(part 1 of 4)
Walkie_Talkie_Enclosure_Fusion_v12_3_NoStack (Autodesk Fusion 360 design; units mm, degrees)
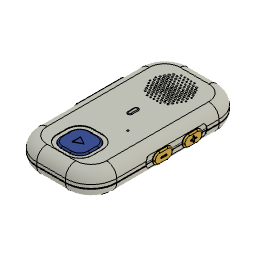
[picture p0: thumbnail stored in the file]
part number: 2026-09-08-15-04-45-721
part number: 2026-09-08-15-04-46-164
part number: 2026-09-08-15-05-02-380
part number: 2026-09-08-15-05-38-058
part number: 2026-09-08-15-05-41-092
part number: 2026-09-08-15-05-42-107
part number: 2026-09-08-15-05-45-542
part number: 2026-09-08-15-05-51-453
part number: 2026-09-08-15-05-57-566
part number: 2026-09-08-15-06-02-599
part number: 2026-09-08-15-06-07-408
part number: 2026-09-08-15-06-08-245
part number: 2026-09-08-15-06-09-018
part number: 2026-09-08-15-06-09-783
part number: 2026-09-08-15-06-10-541
part number: 2026-09-08-15-06-11-278
part number: 2026-09-08-15-06-11-947
part number: 2026-09-08-15-06-12-711
part number: 2026-09-08-15-06-13-510
part number: 2026-09-08-15-06-14-360
parameter "caseWidth" = 78 comment "Overall enclosure width"
parameter "caseHeight" = 150 comment "Overall enclosure height"
parameter "caseDepth" = 24 comment "No-stack package depth from exact installed hardware"
parameter "wallThickness" = 2.2 comment "Nominal enclosure wall"
parameter "sideControlPocketDepth" = 0.75 comment "Recess depth providing full side-button hard travel"
parameter "sideControlPocketFloor" = 1.45 comment "Minimum local side-wall floor below control recesses"
parameter "frontBackSplit" = 12 comment "Centered front/back split line"
parameter "seamOverlap" = 1.25 comment "Continuous guarded lap-seam overlap"
parameter "seamHiddenRadialClearance" = 0.2 comment "Assembly clearance concealed behind lap seam"
parameter "speakerDiameter" = 40 comment "Measured supplied Samesky frame diameter"
parameter "grilleFieldDiameter" = 39.2 comment "Approved coarse halftone W field diameter"
parameter "grillePitch" = 3.2 comment "Nearest-neighbor triangular-lattice pitch"
parameter "grilleHoleSmall" = 1.4 comment "Approved small grille perforation"
parameter "grilleHoleMedium" = 1.8 comment "Approved medium grille perforation"
parameter "grilleHoleLarge" = 2.2 comment "Approved W-core grille perforation"
parameter "grilleMinimumWeb" = 1 comment "Minimum web between adjacent 2.2 mm holes"
parameter "grilleWCoreHalfWidth" = 2.75 comment "Large-dot distance band around W centerlines"
parameter "grilleWHaloHalfWidth" = 6.5 comment "Medium-dot distance band around W centerlines"
parameter "pcbWidth" = 60.02 comment "Measured supplied PCB substrate width"
parameter "pcbHeight" = 80.02 comment "Measured supplied PCB substrate height"
parameter "fitClearance" = 0.25 comment "Per-side static FDM/SLS fit allowance"
parameter "slidingClearance" = 0.2 comment "Per-side moving-interface allowance"
parameter "buttonRestGap" = 0.14 comment "Cap-to-actuator clearance at rest"
parameter "sideSwitchMaxPretravel" = 0.45 comment "Omron B3F-3150 worst-case pretravel"
parameter "frontSwitchMaxPretravel" = 0.5 comment "Omron B3F-4000 worst-case pretravel"
parameter "sideButtonHardTravel" = 0.65 comment "Rest gap + maximum pretravel + 0.06 mm actuation margin"
parameter "frontButtonHardTravel" = 0.7 comment "Rest gap + maximum pretravel + 0.06 mm actuation margin"
parameter "sideActuatorCenterZ" = 15.2 comment "Measured installed B3F-3150 actuator center"
parameter "sideActuatorOpening" = 2.8 comment "Measured 2.40 mm actuator span plus sliding clearance"
parameter "ledBodyDiameter" = 5 comment "Measured Kingbright LED body"
parameter "ledFlangeDiameter" = 5.9 comment "Measured Kingbright LED flange"
parameter "batteryWidthMeasured" = 60.02 comment "Installed rigid battery body from supplied STL"
parameter "batteryHeightMeasured" = 36.02 comment "Installed rigid battery body from supplied STL"
parameter "batteryDepthMeasured" = 8.42 comment "Installed rigid battery body from supplied STL"
parameter "batteryBoardPlanGap" = 1.3 comment "Two fit allowances plus printable shared divider"
parameter "noStackDividerThickness" = 0.8 comment "Shared PCB +Y / battery -Y locator"
parameter "pcbNoStackShiftY" = -20.04 comment "PCB relocation eliminating battery/board overlap"
parameter "pcbFrontSwitchClearanceZ" = 0.25 comment "Clearance between front switch and shifted PCB envelope"
parameter "pcbNoStackShiftZ" = 2.77 comment "Rearward PCB shift clearing the retained front switch"
parameter "usbConnectorCenterY" = -41.0543 comment "Measured USB component center after PCB relocation"
parameter "usbConnectorCenterZ" = 15.4464 comment "Measured USB component center after PCB relocation"
parameter "usbOpeningWidth" = 9.38 comment "Measured connector Y span plus sliding clearance"
parameter "usbOpeningHeight" = 4.793 comment "Measured connector Z span plus sliding clearance"
parameter "usbShellRearDatumX" = 22.4773 comment "Exact rear face of supplied USB-C metal shell"
parameter "usbReactionClearanceX" = 0.2 comment "Connector-shell to case reaction-bridge clearance"
parameter "usbReactionPinClearanceZ" = 0.25 comment "Vertical clearance above the exact signal-pin envelope"
parameter "usbReactionBridgeThickness" = 2.2 comment "Integral back-shell USB insertion-load bridge"
parameter "usbLocalRecessDepth" = 2.7527 comment "Depth required for full 6.65 mm plug-shell seating"
parameter "minimumRibThickness" = 1.2 comment "Prototype FDM/SLS structural rib target"
parameter "minimumContactFillet" = 0.45 comment "No sharp rib at battery/film contact"
parameter "suppliedLeadMaxWidth" = 4.8 comment "Measured battery lead/connector routing envelope"
parameter "cableChannelClearWidth" = 5.3 comment "Measured lead envelope plus two fit clearances"
parameter "cableRailHeight" = 3.4 comment "Open-ended front-shell harness channel height"
parameter "speakerGasketPocketDepth" = 0.3 comment "Closed-cell acoustic gasket seat depth"
parameter "microphoneGasketPocketDepth" = 0.3 comment "Acoustic gasket/mesh seat depth"
parameter "batterySoftPadPocketDepth" = 0.45 comment "Replaceable nonabrasive foam-pad location"
parameter "batteryServiceReliefWidth" = 20 comment "Central removal access between retained top-rail lands"
parameter "rearWordmarkWidth" = 42 comment "Text-only WALKIE ONE wordmark from supplied lockup"
parameter "rearWordmarkCenterY" = -52 comment "Final WALKIE ONE vertical position"
parameter "rearWordmarkDebossDepth" = 0.35 comment "Shallow printable rear engraving"
parameter "rearTaglineHeight" = 1.6 comment "Small upright Designed in Los Angeles lettering"
parameter "rearTaglineCenterY" = -58.5 comment "Centered origin line beneath WALKIE ONE"
parameter "rearTaglineDebossDepth" = 0.25 comment "Subordinate shallow rear engraving"
sketch "Outer Housing" plane through (0, 0, 0) normal (0, 0, 1) x axis (1, 0, 0)
  line L1 (14, -75) -> (-14, -75)
  line L2 (39, 50) -> (39, -50)
  line L3 (-14, 75) -> (14, 75)
  line L4 (-39, -50) -> (-39, 50)
  arc A1 centre (14, -50) radius 25 clockwise from (39, -50) to (14, -75)
  arc A2 centre (14, 50) radius 25 clockwise from (14, 75) to (39, 50)
  arc A3 centre (-14, 50) radius 25 clockwise from (-39, 50) to (-14, 75)
  arc A4 centre (-14, -50) radius 25 clockwise from (-14, -75) to (-39, -50)
extrude "Extrude1" new body sketch "Outer Housing" blind 12
fillet "Fillet1" radius 10
sketch "Front Cavity" plane through (0, 0, 0) normal (0, 0, 1) x axis (1, 0, 0)
  line L1 (14, -72.8) -> (-14, -72.8)
  line L2 (36.8, 50) -> (36.8, -50)
  line L3 (-14, 72.8) -> (14, 72.8)
  line L4 (-36.8, -50) -> (-36.8, 50)
  arc A1 centre (14, -50) radius 22.8 clockwise from (36.8, -50) to (14, -72.8)
  arc A2 centre (14, 50) radius 22.8 clockwise from (14, 72.8) to (36.8, 50)
  arc A3 centre (-14, 50) radius 22.8 clockwise from (-36.8, 50) to (-14, 72.8)
  arc A4 centre (-14, -50) radius 22.8 clockwise from (-14, -72.8) to (-36.8, -50)
extrude "Extrude2" new body sketch "Front Cavity" blind 10 from offset 2.2
fillet "Fillet2" radius 7.8
combine "Combine1"
sketch "Continuous Exterior Seam Guard Collar Sketch" plane through (0, 0, 0) normal (0, 0, 1) x axis (1, 0, 0)
  line L1 (14, -75) -> (-14, -75)
  line L2 (39, 50) -> (39, -50)
  line L3 (-14, 75) -> (14, 75)
  line L4 (-39, -50) -> (-39, 50)
  line L5 (14, -74) -> (-14, -74)
  line L6 (38, 50) -> (38, -50)
  line L7 (-14, 74) -> (14, 74)
  line L8 (-38, -50) -> (-38, 50)
  arc A1 centre (14, -50) radius 25 clockwise from (39, -50) to (14, -75)
  arc A2 centre (14, 50) radius 25 clockwise from (14, 75) to (39, 50)
  arc A3 centre (-14, 50) radius 25 clockwise from (-39, 50) to (-14, 75)
  arc A4 centre (-14, -50) radius 25 clockwise from (-14, -75) to (-39, -50)
  arc A5 centre (14, -50) radius 24 clockwise from (38, -50) to (14, -74)
  arc A6 centre (14, 50) radius 24 clockwise from (14, 74) to (38, 50)
  arc A7 centre (-14, 50) radius 24 clockwise from (-38, 50) to (-14, 74)
  arc A8 centre (-14, -50) radius 24 clockwise from (-14, -74) to (-38, -50)
extrude "Extrude3" add sketch "Continuous Exterior Seam Guard Collar Sketch" blind 1.65 from offset 11.6
sketch "Speaker Seat Solid Sketch" plane through (0, 0, 0) normal (0, 0, 1) x axis (1, 0, 0)
  circle C1 centre (0, 42) radius 23
extrude "Extrude4" add sketch "Speaker Seat Solid Sketch" blind 2.2 from offset 1.6
sketch "Speaker Seat Center Pocket Sketch" plane through (0, 0, 0) normal (0, 0, 1) x axis (1, 0, 0)
  circle C1 centre (0, 42) radius 20.3
extrude "Extrude5" cut sketch "Speaker Seat Center Pocket Sketch" blind 1.8 from offset 2.2
sketch "Speaker Terminal Hidden Relief Sketch" plane through (0, 0, 0) normal (0, 0, 1) x axis (1, 0, 0)
  line L1 (6.2, 18.45) -> (-6.2, 18.45)
  line L2 (6.5, 22.95) -> (6.5, 18.75)
  line L3 (-6.2, 23.25) -> (6.2, 23.25)
  line L4 (-6.5, 18.75) -> (-6.5, 22.95)
  arc A1 centre (6.2, 18.75) radius 0.3 clockwise from (6.5, 18.75) to (6.2, 18.45)
  arc A2 centre (6.2, 22.95) radius 0.3 clockwise from (6.2, 23.25) to (6.5, 22.95)
  arc A3 centre (-6.2, 22.95) radius 0.3 clockwise from (-6.5, 22.95) to (-6.2, 23.25)
  arc A4 centre (-6.2, 18.75) radius 0.3 clockwise from (-6.2, 18.45) to (-6.5, 18.75)
extrude "Extrude6" cut sketch "Speaker Terminal Hidden Relief Sketch" blind 1.9 from offset 2.2
sketch "Speaker Terminal Hidden Relief Sketch (1)" plane through (0, 0, 0) normal (0, 0, 1) x axis (1, 0, 0)
  line L1 (6.2, 58.75) -> (-6.2, 58.75)
  line L2 (6.5, 69.25) -> (6.5, 59.05)
  line L3 (-6.2, 69.55) -> (6.2, 69.55)
  line L4 (-6.5, 59.05) -> (-6.5, 69.25)
  arc A1 centre (6.2, 59.05) radius 0.3 clockwise from (6.5, 59.05) to (6.2, 58.75)
  arc A2 centre (6.2, 69.25) radius 0.3 clockwise from (6.2, 69.55) to (6.5, 69.25)
  arc A3 centre (-6.2, 69.25) radius 0.3 clockwise from (-6.5, 69.25) to (-6.2, 69.55)
  arc A4 centre (-6.2, 59.05) radius 0.3 clockwise from (-6.2, 58.75) to (-6.5, 59.05)
extrude "Extrude7" cut sketch "Speaker Terminal Hidden Relief Sketch (1)" blind 1.9 from offset 2.2
sketch "Speaker Acoustic Gasket Pocket Sketch" plane through (0, 0, 0) normal (0, 0, 1) x axis (1, 0, 0)
  circle C1 centre (0, 42) radius 22.1
  circle C2 centre (0, 42) radius 20.3
extrude "Extrude8" cut sketch "Speaker Acoustic Gasket Pocket Sketch" blind 0.3 from offset 2.2
sketch "Speaker Snap Post Sketch" plane through (0, 0, 0) normal (0, 0, 1) x axis (1, 0, 0)
  circle C1 centre (15.27, 57.27) radius 1.5
extrude "Extrude9" add sketch "Speaker Snap Post Sketch" blind 5.75 from offset 2
sketch "Speaker Snap Lip Sketch" plane through (0, 0, 0) normal (0, 0, 1) x axis (1, 0, 0)
  circle C1 centre (15.27, 57.27) radius 2.1
extrude "Extrude10" add sketch "Speaker Snap Lip Sketch" blind 0.45 from offset 7.45
sketch "Speaker Snap Post Sketch (1)" plane through (0, 0, 0) normal (0, 0, 1) x axis (1, 0, 0)
  circle C1 centre (-15.27, 57.27) radius 1.5
extrude "Extrude11" add sketch "Speaker Snap Post Sketch (1)" blind 5.75 from offset 2
sketch "Speaker Snap Lip Sketch (1)" plane through (0, 0, 0) normal (0, 0, 1) x axis (1, 0, 0)
  circle C1 centre (-15.27, 57.27) radius 2.1
extrude "Extrude12" add sketch "Speaker Snap Lip Sketch (1)" blind 0.45 from offset 7.45
sketch "Speaker Snap Post Sketch (2)" plane through (0, 0, 0) normal (0, 0, 1) x axis (1, 0, 0)
  circle C1 centre (15.27, 26.73) radius 1.5
extrude "Extrude13" add sketch "Speaker Snap Post Sketch (2)" blind 5.75 from offset 2
sketch "Speaker Snap Lip Sketch (2)" plane through (0, 0, 0) normal (0, 0, 1) x axis (1, 0, 0)
  circle C1 centre (15.27, 26.73) radius 2.1
extrude "Extrude14" add sketch "Speaker Snap Lip Sketch (2)" blind 0.45 from offset 7.45
sketch "Speaker Snap Post Sketch (3)" plane through (0, 0, 0) normal (0, 0, 1) x axis (1, 0, 0)
  circle C1 centre (-15.27, 26.73) radius 1.5
extrude "Extrude15" add sketch "Speaker Snap Post Sketch (3)" blind 5.75 from offset 2
sketch "Speaker Snap Lip Sketch (3)" plane through (0, 0, 0) normal (0, 0, 1) x axis (1, 0, 0)
  circle C1 centre (-15.27, 26.73) radius 2.1
extrude "Extrude16" add sketch "Speaker Snap Lip Sketch (3)" blind 0.45 from offset 7.45
sketch "Coarse Three-Size Halftone W Grille 01" plane through (0, 0, 0) normal (0, 0, 1) x axis (1, 0, 0)
  circle C1 centre (-6.4, 25.3723) radius 0.7
  circle C2 centre (-3.2, 25.3723) radius 0.7
  circle C3 centre (0, 25.3723) radius 0.7
  circle C4 centre (3.2, 25.3723) radius 0.7
  circle C5 centre (6.4, 25.3723) radius 0.7
  circle C6 centre (-11.2, 28.1436) radius 0.9
  circle C7 centre (-8, 28.1436) radius 0.9
  circle C8 centre (-4.8, 28.1436) radius 0.9
  circle C9 centre (-1.6, 28.1436) radius 0.7
  circle C10 centre (1.6, 28.1436) radius 0.7
  circle C11 centre (4.8, 28.1436) radius 0.9
  circle C12 centre (8, 28.1436) radius 0.9
  circle C13 centre (11.2, 28.1436) radius 0.9
  circle C14 centre (-12.8, 30.9149) radius 0.9
  circle C15 centre (-9.6, 30.9149) radius 0.9
  circle C16 centre (-6.4, 30.9149) radius 1.1
  circle C17 centre (-3.2, 30.9149) radius 0.9
  circle C18 centre (0, 30.9149) radius 0.7
  circle C19 centre (3.2, 30.9149) radius 0.9
  circle C20 centre (6.4, 30.9149) radius 1.1
  circle C21 centre (9.6, 30.9149) radius 0.9
  circle C22 centre (12.8, 30.9149) radius 0.9
  circle C23 centre (-14.4, 33.6862) radius 0.7
  circle C24 centre (-11.2, 33.6862) radius 0.9
  circle C25 centre (-8, 33.6862) radius 1.1
  circle C26 centre (-4.8, 33.6862) radius 1.1
  circle C27 centre (-1.6, 33.6862) radius 0.9
  circle C28 centre (1.6, 33.6862) radius 0.9
  circle C29 centre (4.8, 33.6862) radius 1.1
  circle C30 centre (8, 33.6862) radius 1.1
  circle C31 centre (11.2, 33.6862) radius 0.9
  circle C32 centre (14.4, 33.6862) radius 0.7
  circle C33 centre (-16, 36.4574) radius 0.7
  circle C34 centre (-12.8, 36.4574) radius 0.9
  circle C35 centre (-9.6, 36.4574) radius 1.1
  circle C36 centre (-6.4, 36.4574) radius 1.1
  circle C37 centre (-3.2, 36.4574) radius 1.1
  circle C38 centre (0, 36.4574) radius 0.9
  circle C39 centre (3.2, 36.4574) radius 1.1
  circle C40 centre (6.4, 36.4574) radius 1.1
  circle C41 centre (9.6, 36.4574) radius 1.1
  circle C42 centre (12.8, 36.4574) radius 0.9
  circle C43 centre (16, 36.4574) radius 0.7
  circle C44 centre (-17.6, 39.2287) radius 0.7
  circle C45 centre (-14.4, 39.2287) radius 0.9
  circle C46 centre (-11.2, 39.2287) radius 1.1
  circle C47 centre (-8, 39.2287) radius 1.1
  circle C48 centre (-4.8, 39.2287) radius 1.1
  circle C49 centre (-1.6, 39.2287) radius 1.1
  circle C50 centre (1.6, 39.2287) radius 1.1
  circle C51 centre (4.8, 39.2287) radius 1.1
  circle C52 centre (8, 39.2287) radius 1.1
  circle C53 centre (11.2, 39.2287) radius 1.1
  circle C54 centre (14.4, 39.2287) radius 0.9
  circle C55 centre (17.6, 39.2287) radius 0.7
  circle C56 centre (-16, 42) radius 0.9
  circle C57 centre (-12.8, 42) radius 0.9
  circle C58 centre (-9.6, 42) radius 1.1
  circle C59 centre (-6.4, 42) radius 0.9
  circle C60 centre (-3.2, 42) radius 1.1
  circle C61 centre (0, 42) radius 1.1
  circle C62 centre (3.2, 42) radius 1.1
  circle C63 centre (6.4, 42) radius 0.9
  circle C64 centre (9.6, 42) radius 1.1
  circle C65 centre (12.8, 42) radius 0.9
  circle C66 centre (16, 42) radius 0.9
  circle C67 centre (-17.6, 44.7713) radius 0.7
  circle C68 centre (-14.4, 44.7713) radius 0.9
  circle C69 centre (-11.2, 44.7713) radius 1.1
  circle C70 centre (-8, 44.7713) radius 1.1
  circle C71 centre (-4.8, 44.7713) radius 0.9
  circle C72 centre (-1.6, 44.7713) radius 1.1
  circle C73 centre (1.6, 44.7713) radius 1.1
  circle C74 centre (4.8, 44.7713) radius 0.9
  circle C75 centre (8, 44.7713) radius 1.1
  circle C76 centre (11.2, 44.7713) radius 1.1
  circle C77 centre (14.4, 44.7713) radius 0.9
  circle C78 centre (17.6, 44.7713) radius 0.7
  circle C79 centre (-16, 47.5426) radius 0.9
  circle C80 centre (-12.8, 47.5426) radius 1.1
  circle C81 centre (-9.6, 47.5426) radius 1.1
  circle C82 centre (-6.4, 47.5426) radius 0.9
  circle C83 centre (-3.2, 47.5426) radius 0.9
  circle C84 centre (0, 47.5426) radius 0.9
  circle C85 centre (3.2, 47.5426) radius 0.9
  circle C86 centre (6.4, 47.5426) radius 0.9
  circle C87 centre (9.6, 47.5426) radius 1.1
  circle C88 centre (12.8, 47.5426) radius 1.1
  circle C89 centre (16, 47.5426) radius 0.9
  circle C90 centre (-14.4, 50.3138) radius 1.1
  circle C91 centre (-11.2, 50.3138) radius 1.1
  circle C92 centre (-8, 50.3138) radius 0.9
  circle C93 centre (-4.8, 50.3138) radius 0.7
  circle C94 centre (-1.6, 50.3138) radius 0.7
  circle C95 centre (1.6, 50.3138) radius 0.7
  circle C96 centre (4.8, 50.3138) radius 0.7
  circle C97 centre (8, 50.3138) radius 0.9
  circle C98 centre (11.2, 50.3138) radius 1.1
  circle C99 centre (14.4, 50.3138) radius 1.1
  circle C100 centre (-12.8, 53.0851) radius 1.1
  circle C101 centre (-9.6, 53.0851) radius 0.9
  circle C102 centre (-6.4, 53.0851) radius 0.9
  circle C103 centre (-3.2, 53.0851) radius 0.7
  circle C104 centre (0, 53.0851) radius 0.7
  circle C105 centre (3.2, 53.0851) radius 0.7
  circle C106 centre (6.4, 53.0851) radius 0.9
  circle C107 centre (9.6, 53.0851) radius 0.9
  circle C108 centre (12.8, 53.0851) radius 1.1
  circle C109 centre (-11.2, 55.8564) radius 0.9
  circle C110 centre (-8, 55.8564) radius 0.9
  circle C111 centre (-4.8, 55.8564) radius 0.7
  circle C112 centre (-1.6, 55.8564) radius 0.7
  circle C113 centre (1.6, 55.8564) radius 0.7
  circle C114 centre (4.8, 55.8564) radius 0.7
  circle C115 centre (8, 55.8564) radius 0.9
  circle C116 centre (11.2, 55.8564) radius 0.9
  circle C117 centre (-6.4, 58.6277) radius 0.7
  circle C118 centre (-3.2, 58.6277) radius 0.7
  circle C119 centre (0, 58.6277) radius 0.7
  circle C120 centre (3.2, 58.6277) radius 0.7
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extrude "Extrude17" cut sketch "Coarse Three-Size Halftone W Grille 01" blind 3.2
sketch "Quiet Orb Status Light Opening Sketch" plane through (0, 0, 0) normal (0, 0, 1) x axis (1, 0, 0)
  line L1 (0.05, -0.2) -> (-0.05, -0.2)
  line L2 (2.2, 8.05) -> (2.2, 1.95)
  line L3 (-0.05, 10.2) -> (0.05, 10.2)
  line L4 (-2.2, 1.95) -> (-2.2, 8.05)
  arc A1 centre (0.05, 1.95) radius 2.15 clockwise from (2.2, 1.95) to (0.05, -0.2)
  arc A2 centre (0.05, 8.05) radius 2.15 clockwise from (0.05, 10.2) to (2.2, 8.05)
  arc A3 centre (-0.05, 8.05) radius 2.15 clockwise from (-2.2, 8.05) to (-0.05, 10.2)
  arc A4 centre (-0.05, 1.95) radius 2.15 clockwise from (-0.05, -0.2) to (-2.2, 1.95)
extrude "Extrude18" cut sketch "Quiet Orb Status Light Opening Sketch" blind 3
sketch "Microphone Port Sketch" plane through (0, 0, 0) normal (0, 0, 1) x axis (1, 0, 0)
  circle C1 centre (-14, -14) radius 0.9
extrude "Extrude19" cut sketch "Microphone Port Sketch" blind 3.2
sketch "Microphone Acoustic Gasket Pocket Sketch" plane through (0, 0, 0) normal (0, 0, 1) x axis (1, 0, 0)
  circle C1 centre (-14, -14) radius 2.75
  circle C2 centre (-14, -14) radius 1.1
extrude "Extrude20" cut sketch "Microphone Acoustic Gasket Pocket Sketch" blind 0.35 from offset 1.9
sketch "Sculpted Action Thumb Well Sketch" plane through (0, 0, 0) normal (0, 0, 1) x axis (1, 0, 0)
  line L1 (5, -64.5) -> (-5, -64.5)
  line L2 (17.5, -42) -> (17.5, -52)
  line L3 (-5, -29.5) -> (5, -29.5)
  line L4 (-17.5, -52) -> (-17.5, -42)
  arc A1 centre (5, -52) radius 12.5 clockwise from (17.5, -52) to (5, -64.5)
  arc A2 centre (5, -42) radius 12.5 clockwise from (5, -29.5) to (17.5, -42)
  arc A3 centre (-5, -42) radius 12.5 clockwise from (-17.5, -42) to (-5, -29.5)
  arc A4 centre (-5, -52) radius 12.5 clockwise from (-5, -64.5) to (-17.5, -52)
extrude "Extrude21" cut sketch "Sculpted Action Thumb Well Sketch" blind 0.58
sketch "Quiet Orb Action Button Opening Sketch" plane through (0, 0, 0) normal (0, 0, 1) x axis (1, 0, 0)
  line L1 (4.4, -61.1) -> (-4.4, -61.1)
  line L2 (14.1, -42.6) -> (14.1, -51.4)
  line L3 (-4.4, -32.9) -> (4.4, -32.9)
  line L4 (-14.1, -51.4) -> (-14.1, -42.6)
  arc A1 centre (4.4, -51.4) radius 9.7 clockwise from (14.1, -51.4) to (4.4, -61.1)
  arc A2 centre (4.4, -42.6) radius 9.7 clockwise from (4.4, -32.9) to (14.1, -42.6)
  arc A3 centre (-4.4, -42.6) radius 9.7 clockwise from (-14.1, -42.6) to (-4.4, -32.9)
  arc A4 centre (-4.4, -51.4) radius 9.7 clockwise from (-4.4, -61.1) to (-14.1, -51.4)
extrude "Extrude22" cut sketch "Quiet Orb Action Button Opening Sketch" blind 3
sketch "LED Guide Tube Solid Sketch" plane through (0, 0, 0) normal (0, 0, 1) x axis (1, 0, 0)
  circle C1 centre (0, 5) radius 4
extrude "Extrude23" add sketch "LED Guide Tube Solid Sketch" blind 8.9 from offset 1.8
sketch "LED Body Guide Bore Sketch" plane through (0, 0, 0) normal (0, 0, 1) x axis (1, 0, 0)
  circle C1 centre (0, 5) radius 2.65
extrude "Extrude24" cut sketch "LED Body Guide Bore Sketch" blind 7 from offset 2.05
sketch "LED Flange Pocket Sketch" plane through (0, 0, 0) normal (0, 0, 1) x axis (1, 0, 0)
  circle C1 centre (0, 5) radius 3.2
extrude "Extrude25" cut sketch "LED Flange Pocket Sketch" blind 2 from offset 9.05
sketch "LED Flange Flex Post Sketch" plane through (0, 0, 0) normal (0, 0, 1) x axis (1, 0, 0)
  line L1 (-3.57, 3.9) -> (-3.73, 3.9)
  line L2 (-3.15, 5.68) -> (-3.15, 4.32)
  line L3 (-3.73, 6.1) -> (-3.57, 6.1)
  line L4 (-4.15, 4.32) -> (-4.15, 5.68)
  arc A1 centre (-3.57, 4.32) radius 0.42 clockwise from (-3.15, 4.32) to (-3.57, 3.9)
  arc A2 centre (-3.57, 5.68) radius 0.42 clockwise from (-3.57, 6.1) to (-3.15, 5.68)
  arc A3 centre (-3.73, 5.68) radius 0.42 clockwise from (-4.15, 5.68) to (-3.73, 6.1)
  arc A4 centre (-3.73, 4.32) radius 0.42 clockwise from (-3.73, 3.9) to (-4.15, 4.32)
extrude "Extrude26" add sketch "LED Flange Flex Post Sketch" blind 2.3 from offset 8.8
sketch "LED Flange Flex Post Sketch (1)" plane through (0, 0, 0) normal (0, 0, 1) x axis (1, 0, 0)
  line L1 (3.73, 3.9) -> (3.57, 3.9)
  line L2 (4.15, 5.68) -> (4.15, 4.32)
  line L3 (3.57, 6.1) -> (3.73, 6.1)
  line L4 (3.15, 4.32) -> (3.15, 5.68)
  arc A1 centre (3.73, 4.32) radius 0.42 clockwise from (4.15, 4.32) to (3.73, 3.9)
  arc A2 centre (3.73, 5.68) radius 0.42 clockwise from (3.73, 6.1) to (4.15, 5.68)
  arc A3 centre (3.57, 5.68) radius 0.42 clockwise from (3.15, 5.68) to (3.57, 6.1)
  arc A4 centre (3.57, 4.32) radius 0.42 clockwise from (3.57, 3.9) to (3.15, 4.32)
extrude "Extrude27" add sketch "LED Flange Flex Post Sketch (1)" blind 2.3 from offset 8.8
sketch "LED Captive Flange Hook Sketch" plane through (0, 0, 0) normal (0, 0, 1) x axis (1, 0, 0)
  line L1 (-2.87, 3.9) -> (-3.73, 3.9)
  line L2 (-2.45, 5.68) -> (-2.45, 4.32)
  line L3 (-3.73, 6.1) -> (-2.87, 6.1)
  line L4 (-4.15, 4.32) -> (-4.15, 5.68)
  arc A1 centre (-2.87, 4.32) radius 0.42 clockwise from (-2.45, 4.32) to (-2.87, 3.9)
  arc A2 centre (-2.87, 5.68) radius 0.42 clockwise from (-2.87, 6.1) to (-2.45, 5.68)
  arc A3 centre (-3.73, 5.68) radius 0.42 clockwise from (-4.15, 5.68) to (-3.73, 6.1)
  arc A4 centre (-3.73, 4.32) radius 0.42 clockwise from (-3.73, 3.9) to (-4.15, 4.32)
extrude "Extrude28" add sketch "LED Captive Flange Hook Sketch" blind 0.5 from offset 10.55
sketch "LED Captive Flange Hook Sketch (1)" plane through (0, 0, 0) normal (0, 0, 1) x axis (1, 0, 0)
  line L1 (3.73, 3.9) -> (2.87, 3.9)
  line L2 (4.15, 5.68) -> (4.15, 4.32)
  line L3 (2.87, 6.1) -> (3.73, 6.1)
  line L4 (2.45, 4.32) -> (2.45, 5.68)
  arc A1 centre (3.73, 4.32) radius 0.42 clockwise from (4.15, 4.32) to (3.73, 3.9)
  arc A2 centre (3.73, 5.68) radius 0.42 clockwise from (3.73, 6.1) to (4.15, 5.68)
  arc A3 centre (2.87, 5.68) radius 0.42 clockwise from (2.45, 5.68) to (2.87, 6.1)
  arc A4 centre (2.87, 4.32) radius 0.42 clockwise from (2.87, 3.9) to (2.45, 4.32)
extrude "Extrude29" add sketch "LED Captive Flange Hook Sketch (1)" blind 0.5 from offset 10.55
sketch "Restore Quiet Orb Status Aperture Sketch" plane through (0, 0, 0) normal (0, 0, 1) x axis (1, 0, 0)
  line L1 (0.05, -0.2) -> (-0.05, -0.2)
  line L2 (2.2, 8.05) -> (2.2, 1.95)
  line L3 (-0.05, 10.2) -> (0.05, 10.2)
  line L4 (-2.2, 1.95) -> (-2.2, 8.05)
  arc A1 centre (0.05, 1.95) radius 2.15 clockwise from (2.2, 1.95) to (0.05, -0.2)
  arc A2 centre (0.05, 8.05) radius 2.15 clockwise from (0.05, 10.2) to (2.2, 8.05)
  arc A3 centre (-0.05, 8.05) radius 2.15 clockwise from (-2.2, 8.05) to (-0.05, 10.2)
  arc A4 centre (-0.05, 1.95) radius 2.15 clockwise from (-0.05, -0.2) to (-2.2, 1.95)
extrude "Extrude30" cut sketch "Restore Quiet Orb Status Aperture Sketch" blind 3.2
sketch "Microphone Breakout Pocket Sketch" plane through (0, 0, 0) normal (0, 0, 1) x axis (1, 0, 0)
  line L1 (-6.4, -21.2) -> (-21.6, -21.2)
  line L2 (-4.9, -8.3) -> (-4.9, -19.7)
  line L3 (-21.6, -6.8) -> (-6.4, -6.8)
  line L4 (-23.1, -19.7) -> (-23.1, -8.3)
  line L5 (-6.55, -20.6) -> (-21.45, -20.6)
  line L6 (-5.5, -8.45) -> (-5.5, -19.55)
  line L7 (-21.45, -7.4) -> (-6.55, -7.4)
  line L8 (-22.5, -19.55) -> (-22.5, -8.45)
  arc A1 centre (-6.4, -19.7) radius 1.5 clockwise from (-4.9, -19.7) to (-6.4, -21.2)
  arc A2 centre (-6.4, -8.3) radius 1.5 clockwise from (-6.4, -6.8) to (-4.9, -8.3)
  arc A3 centre (-21.6, -8.3) radius 1.5 clockwise from (-23.1, -8.3) to (-21.6, -6.8)
  arc A4 centre (-21.6, -19.7) radius 1.5 clockwise from (-21.6, -21.2) to (-23.1, -19.7)
  arc A5 centre (-6.55, -19.55) radius 1.05 clockwise from (-5.5, -19.55) to (-6.55, -20.6)
  arc A6 centre (-6.55, -8.45) radius 1.05 clockwise from (-6.55, -7.4) to (-5.5, -8.45)
  arc A7 centre (-21.45, -8.45) radius 1.05 clockwise from (-22.5, -8.45) to (-21.45, -7.4)
  arc A8 centre (-21.45, -19.55) radius 1.05 clockwise from (-21.45, -20.6) to (-22.5, -19.55)
extrude "Extrude31" add sketch "Microphone Breakout Pocket Sketch" blind 3.2 from offset 2
sketch "Microphone Snap Lip Sketch" plane through (0, 0, 0) normal (0, 0, 1) x axis (1, 0, 0)
  line L1 (-12.5, -20.9) -> (-15.5, -20.9)
  line L2 (-12, -20.1) -> (-12, -20.4)
  line L3 (-15.5, -19.6) -> (-12.5, -19.6)
  line L4 (-16, -20.4) -> (-16, -20.1)
  arc A1 centre (-12.5, -20.4) radius 0.5 clockwise from (-12, -20.4) to (-12.5, -20.9)
  arc A2 centre (-12.5, -20.1) radius 0.5 clockwise from (-12.5, -19.6) to (-12, -20.1)
  arc A3 centre (-15.5, -20.1) radius 0.5 clockwise from (-16, -20.1) to (-15.5, -19.6)
  arc A4 centre (-15.5, -20.4) radius 0.5 clockwise from (-15.5, -20.9) to (-16, -20.4)
extrude "Extrude32" add sketch "Microphone Snap Lip Sketch" blind 0.4 from offset 4.95
sketch "Microphone Snap Lip Sketch (1)" plane through (0, 0, 0) normal (0, 0, 1) x axis (1, 0, 0)
  line L1 (-12.5, -8.4) -> (-15.5, -8.4)
  line L2 (-12, -7.6) -> (-12, -7.9)
  line L3 (-15.5, -7.1) -> (-12.5, -7.1)
  line L4 (-16, -7.9) -> (-16, -7.6)
  arc A1 centre (-12.5, -7.9) radius 0.5 clockwise from (-12, -7.9) to (-12.5, -8.4)
  arc A2 centre (-12.5, -7.6) radius 0.5 clockwise from (-12.5, -7.1) to (-12, -7.6)
  arc A3 centre (-15.5, -7.6) radius 0.5 clockwise from (-16, -7.6) to (-15.5, -7.1)
  arc A4 centre (-15.5, -7.9) radius 0.5 clockwise from (-15.5, -8.4) to (-16, -7.9)
extrude "Extrude33" add sketch "Microphone Snap Lip Sketch (1)" blind 0.4 from offset 4.95
sketch "Front Switch Clamp Boss Sketch" plane through (0, 0, 0) normal (0, 0, 1) x axis (1, 0, 0)
  circle C1 centre (-17, -47) radius 2.1
extrude "Extrude34" add sketch "Front Switch Clamp Boss Sketch" blind 8.85 from offset 2
sketch "Front Switch Clamp M2 Pilot Sketch" plane through (0, 0, 0) normal (0, 0, 1) x axis (1, 0, 0)
  circle C1 centre (-17, -47) radius 0.85
extrude "Extrude35" cut sketch "Front Switch Clamp M2 Pilot Sketch" blind 8.4 from offset 2.6
sketch "Front Switch Clamp Boss Sketch (1)" plane through (0, 0, 0) normal (0, 0, 1) x axis (1, 0, 0)
  circle C1 centre (17, -47) radius 2.1
extrude "Extrude36" add sketch "Front Switch Clamp Boss Sketch (1)" blind 8.85 from offset 2
sketch "Front Switch Clamp M2 Pilot Sketch (1)" plane through (0, 0, 0) normal (0, 0, 1) x axis (1, 0, 0)
  circle C1 centre (17, -47) radius 0.85
extrude "Extrude37" cut sketch "Front Switch Clamp M2 Pilot Sketch (1)" blind 8.4 from offset 2.6
sketch "Front Switch Body Reaction Bridge Sketch" plane through (0, 0, 0) normal (0, 0, 1) x axis (1, 0, 0)
  line L1 (16.5, -55) -> (-16.5, -55)
  line L2 (19.5, -42) -> (19.5, -52)
  line L3 (-16.5, -39) -> (16.5, -39)
  line L4 (-19.5, -52) -> (-19.5, -42)
  line L5 (2, -51) -> (-2, -51)
  line L6 (4, -45) -> (4, -49)
  line L7 (-2, -43) -> (2, -43)
  line L8 (-4, -49) -> (-4, -45)
  arc A1 centre (16.5, -52) radius 3 clockwise from (19.5, -52) to (16.5, -55)
  arc A2 centre (16.5, -42) radius 3 clockwise from (16.5, -39) to (19.5, -42)
  arc A3 centre (-16.5, -42) radius 3 clockwise from (-19.5, -42) to (-16.5, -39)
  arc A4 centre (-16.5, -52) radius 3 clockwise from (-16.5, -55) to (-19.5, -52)
  arc A5 centre (2, -49) radius 2 clockwise from (4, -49) to (2, -51)
  arc A6 centre (2, -45) radius 2 clockwise from (2, -43) to (4, -45)
  arc A7 centre (-2, -45) radius 2 clockwise from (-4, -45) to (-2, -43)
  arc A8 centre (-2, -49) radius 2 clockwise from (-2, -51) to (-4, -49)
extrude "Extrude38" add sketch "Front Switch Body Reaction Bridge Sketch" blind 0.2 from offset 3.2
sketch "PTT Interaction Field Sketch" plane through (0, 0, 0) normal (1, 0, 0) x axis (0, 0, -1)
  line L1 (-11.9, -17.5) -> (-12.1, -17.5)
  line L2 (-5.1, 34.7) -> (-5.1, -10.7)
  line L3 (-12.1, 41.5) -> (-11.9, 41.5)
  line L4 (-18.9, -10.7) -> (-18.9, 34.7)
  arc A1 centre (-11.9, -10.7) radius 6.8 clockwise from (-5.1, -10.7) to (-11.9, -17.5)
  arc A2 centre (-11.9, 34.7) radius 6.8 clockwise from (-11.9, 41.5) to (-5.1, 34.7)
  arc A3 centre (-12.1, 34.7) radius 6.8 clockwise from (-18.9, 34.7) to (-12.1, 41.5)
  arc A4 centre (-12.1, -10.7) radius 6.8 clockwise from (-12.1, -17.5) to (-18.9, -10.7)
extrude "Extrude39" cut sketch "PTT Interaction Field Sketch" blind -0.75 (= "-( 0.75 mm )") from offset 39.2
sketch "Unified Volume Interaction Field Sketch" plane through (0, 0, 0) normal (1, 0, 0) x axis (0, 0, -1)
  line L1 (-11.9, -21.25) -> (-12.1, -21.25)
  line L2 (-5.1, 31.45) -> (-5.1, -14.45)
  line L3 (-12.1, 38.25) -> (-11.9, 38.25)
  line L4 (-18.9, -14.45) -> (-18.9, 31.45)
  arc A1 centre (-11.9, -14.45) radius 6.8 clockwise from (-5.1, -14.45) to (-11.9, -21.25)
  arc A2 centre (-11.9, 31.45) radius 6.8 clockwise from (-11.9, 38.25) to (-5.1, 31.45)
  arc A3 centre (-12.1, 31.45) radius 6.8 clockwise from (-18.9, 31.45) to (-12.1, 38.25)
  arc A4 centre (-12.1, -14.45) radius 6.8 clockwise from (-12.1, -21.25) to (-18.9, -14.45)
extrude "Extrude40" cut sketch "Unified Volume Interaction Field Sketch" blind 0.75 from offset -39.2
sketch "Left PTT Through Opening Sketch" plane through (0, 0, 0) normal (1, 0, 0) x axis (0, 0, -1)
  line L1 (-11.9, -13.2) -> (-12.1, -13.2)
  line L2 (-7.5, 32.8) -> (-7.5, -8.8)
  line L3 (-12.1, 37.2) -> (-11.9, 37.2)
  line L4 (-16.5, -8.8) -> (-16.5, 32.8)
  arc A1 centre (-11.9, -8.8) radius 4.4 clockwise from (-7.5, -8.8) to (-11.9, -13.2)
  arc A2 centre (-11.9, 32.8) radius 4.4 clockwise from (-11.9, 37.2) to (-7.5, 32.8)
  arc A3 centre (-12.1, 32.8) radius 4.4 clockwise from (-16.5, 32.8) to (-12.1, 37.2)
  arc A4 centre (-12.1, -8.8) radius 4.4 clockwise from (-12.1, -13.2) to (-16.5, -8.8)
extrude "Extrude41" cut sketch "Left PTT Through Opening Sketch" blind 40
sketch "Volume Up Through Opening Sketch" plane through (0, 0, 0) normal (1, 0, 0) x axis (0, 0, -1)
  line L1 (-11.9, 15.15) -> (-12.1, 15.15)
  line L2 (-7.8, 26.75) -> (-7.8, 19.25)
  line L3 (-12.1, 30.85) -> (-11.9, 30.85)
  line L4 (-16.2, 19.25) -> (-16.2, 26.75)
  arc A1 centre (-11.9, 19.25) radius 4.1 clockwise from (-7.8, 19.25) to (-11.9, 15.15)
  arc A2 centre (-11.9, 26.75) radius 4.1 clockwise from (-11.9, 30.85) to (-7.8, 26.75)
  arc A3 centre (-12.1, 26.75) radius 4.1 clockwise from (-16.2, 26.75) to (-12.1, 30.85)
  arc A4 centre (-12.1, 19.25) radius 4.1 clockwise from (-12.1, 15.15) to (-16.2, 19.25)
extrude "Extrude42" cut sketch "Volume Up Through Opening Sketch" blind -40 (= "-( 40.00 mm )")
sketch "Volume Down Through Opening Sketch" plane through (0, 0, 0) normal (1, 0, 0) x axis (0, 0, -1)
  line L1 (-11.9, -13.85) -> (-12.1, -13.85)
  line L2 (-7.8, -2.25) -> (-7.8, -9.75)
  line L3 (-12.1, 1.85) -> (-11.9, 1.85)
  line L4 (-16.2, -9.75) -> (-16.2, -2.25)
  arc A1 centre (-11.9, -9.75) radius 4.1 clockwise from (-7.8, -9.75) to (-11.9, -13.85)
  arc A2 centre (-11.9, -2.25) radius 4.1 clockwise from (-11.9, 1.85) to (-7.8, -2.25)
  arc A3 centre (-12.1, -2.25) radius 4.1 clockwise from (-16.2, -2.25) to (-12.1, 1.85)
  arc A4 centre (-12.1, -9.75) radius 4.1 clockwise from (-12.1, -13.85) to (-16.2, -9.75)
extrude "Extrude43" cut sketch "Volume Down Through Opening Sketch" blind -40 (= "-( 40.00 mm )")
sketch "USB-C Full-Seating Local Wall Recess Sketch" plane through (0, 0, 0) normal (1, 0, 0) x axis (0, 0, -1)
  line L1 (-15.1964, -47.6793) -> (-15.6964, -47.6793)
  line L2 (-11.7464, -37.8793) -> (-11.7464, -44.2293)
  line L3 (-15.6964, -34.4293) -> (-15.1964, -34.4293)
  line L4 (-19.1464, -44.2293) -> (-19.1464, -37.8793)
  arc A1 centre (-15.1964, -44.2293) radius 3.45 clockwise from (-11.7464, -44.2293) to (-15.1964, -47.6793)
  arc A2 centre (-15.1964, -37.8793) radius 3.45 clockwise from (-15.1964, -34.4293) to (-11.7464, -37.8793)
  arc A3 centre (-15.6964, -37.8793) radius 3.45 clockwise from (-19.1464, -37.8793) to (-15.6964, -34.4293)
  arc A4 centre (-15.6964, -44.2293) radius 3.45 clockwise from (-15.6964, -47.6793) to (-19.1464, -44.2293)
extrude "Extrude44" cut sketch "USB-C Full-Seating Local Wall Recess Sketch" blind -2.9527 (= "-( 2.952733 mm )") from offset 39.2
sketch "Sketch45" plane through (0, 0, 0) normal (1, 0, 0) x axis (0, 0, -1)
  line L1 (-15.3964, -45.7443) -> (-15.4964, -45.7443)
  line L2 (-13.0499, -38.7108) -> (-13.0499, -43.3978)
  line L3 (-15.4964, -36.3643) -> (-15.3964, -36.3643)
  line L4 (-17.8429, -43.3978) -> (-17.8429, -38.7108)
  arc A1 centre (-15.3964, -43.3978) radius 2.3465 clockwise from (-13.0499, -43.3978) to (-15.3964, -45.7443)
  arc A2 centre (-15.3964, -38.7108) radius 2.3465 clockwise from (-15.3964, -36.3643) to (-13.0499, -38.7108)
  arc A3 centre (-15.4964, -38.7108) radius 2.3465 clockwise from (-17.8429, -38.7108) to (-15.4964, -36.3643)
  arc A4 centre (-15.4964, -43.3978) radius 2.3465 clockwise from (-15.4964, -45.7443) to (-17.8429, -43.3978)
extrude "Extrude45" cut sketch "Sketch45" blind 40
sketch "PTT Internal Switch Body Clearance Sketch" plane through (0, 0, 0) normal (1, 0, 0) x axis (0, 0, -1)
  line L1 (-8.49, 6.65) -> (-18.01, 6.65)
  line L2 (-8.04, 16.9) -> (-8.04, 7.1)
  line L3 (-18.01, 17.35) -> (-8.49, 17.35)
  line L4 (-18.46, 7.1) -> (-18.46, 16.9)
  arc A1 centre (-8.49, 7.1) radius 0.45 clockwise from (-8.04, 7.1) to (-8.49, 6.65)
  arc A2 centre (-8.49, 16.9) radius 0.45 clockwise from (-8.49, 17.35) to (-8.04, 16.9)
  arc A3 centre (-18.01, 16.9) radius 0.45 clockwise from (-18.46, 16.9) to (-18.01, 17.35)
  arc A4 centre (-18.01, 7.1) radius 0.45 clockwise from (-18.01, 6.65) to (-18.46, 7.1)
extrude "Extrude46" cut sketch "PTT Internal Switch Body Clearance Sketch" blind 5.1 from offset 31.9
sketch "PTT Switch Cage Anchor Sketch" plane through (0, 0, 0) normal (0, 0, 1) x axis (1, 0, 0)
  line L1 (32, 6.45) -> (31.5, 6.45)
  line L2 (32.35, 7.3) -> (32.35, 6.8)
  line L3 (31.5, 7.65) -> (32, 7.65)
  line L4 (31.15, 6.8) -> (31.15, 7.3)
  arc A1 centre (32, 6.8) radius 0.35 clockwise from (32.35, 6.8) to (32, 6.45)
  arc A2 centre (32, 7.3) radius 0.35 clockwise from (32, 7.65) to (32.35, 7.3)
  arc A3 centre (31.5, 7.3) radius 0.35 clockwise from (31.15, 7.3) to (31.5, 7.65)
  arc A4 centre (31.5, 6.8) radius 0.35 clockwise from (31.5, 6.45) to (31.15, 6.8)
extrude "Extrude47" add sketch "PTT Switch Cage Anchor Sketch" blind 5.59 from offset 2
sketch "PTT Switch Cage Anchor Sketch (1)" plane through (0, 0, 0) normal (0, 0, 1) x axis (1, 0, 0)
  line L1 (32, 16.35) -> (31.5, 16.35)
  line L2 (32.35, 17.2) -> (32.35, 16.7)
  line L3 (31.5, 17.55) -> (32, 17.55)
  line L4 (31.15, 16.7) -> (31.15, 17.2)
  arc A1 centre (32, 16.7) radius 0.35 clockwise from (32.35, 16.7) to (32, 16.35)
  arc A2 centre (32, 17.2) radius 0.35 clockwise from (32, 17.55) to (32.35, 17.2)
  arc A3 centre (31.5, 17.2) radius 0.35 clockwise from (31.15, 17.2) to (31.5, 17.55)
  arc A4 centre (31.5, 16.7) radius 0.35 clockwise from (31.5, 16.35) to (31.15, 16.7)
extrude "Extrude48" add sketch "PTT Switch Cage Anchor Sketch (1)" blind 5.59 from offset 2
sketch "PTT Switch Floor Sketch" plane through (0, 0, 0) normal (0, 0, 1) x axis (1, 0, 0)
  line L1 (36.65, 6.65) -> (31.55, 6.65)
  line L2 (37.1, 16.9) -> (37.1, 7.1)
  line L3 (31.55, 17.35) -> (36.65, 17.35)
  line L4 (31.1, 7.1) -> (31.1, 16.9)
  arc A1 centre (36.65, 7.1) radius 0.45 clockwise from (37.1, 7.1) to (36.65, 6.65)
  arc A2 centre (36.65, 16.9) radius 0.45 clockwise from (36.65, 17.35) to (37.1, 16.9)
  arc A3 centre (31.55, 16.9) radius 0.45 clockwise from (31.1, 16.9) to (31.55, 17.35)
  arc A4 centre (31.55, 7.1) radius 0.45 clockwise from (31.55, 6.65) to (31.1, 7.1)
extrude "Extrude49" add sketch "PTT Switch Floor Sketch" blind 0.55 from offset 7.49
sketch "PTT Switch Inward Backstop Sketch" plane through (0, 0, 0) normal (0, 0, 1) x axis (1, 0, 0)
  line L1 (31.85, 6.65) -> (31.65, 6.65)
  line L2 (32.2, 17) -> (32.2, 7)
  line L3 (31.65, 17.35) -> (31.85, 17.35)
  line L4 (31.3, 7) -> (31.3, 17)
  arc A1 centre (31.85, 7) radius 0.35 clockwise from (32.2, 7) to (31.85, 6.65)
  arc A2 centre (31.85, 17) radius 0.35 clockwise from (31.85, 17.35) to (32.2, 17)
  arc A3 centre (31.65, 17) radius 0.35 clockwise from (31.3, 17) to (31.65, 17.35)
  arc A4 centre (31.65, 7) radius 0.35 clockwise from (31.65, 6.65) to (31.3, 7)
extrude "Extrude50" add sketch "PTT Switch Inward Backstop Sketch" blind 4.51 from offset 7.49
sketch "PTT Switch Side Rail Sketch" plane through (0, 0, 0) normal (0, 0, 1) x axis (1, 0, 0)
  line L1 (36.675, 6.65) -> (32.325, 6.65)
  line L2 (36.975, 7.15) -> (36.975, 6.95)
  line L3 (32.325, 7.45) -> (36.675, 7.45)
  line L4 (32.025, 6.95) -> (32.025, 7.15)
  arc A1 centre (36.675, 6.95) radius 0.3 clockwise from (36.975, 6.95) to (36.675, 6.65)
  arc A2 centre (36.675, 7.15) radius 0.3 clockwise from (36.675, 7.45) to (36.975, 7.15)
  arc A3 centre (32.325, 7.15) radius 0.3 clockwise from (32.025, 7.15) to (32.325, 7.45)
  arc A4 centre (32.325, 6.95) radius 0.3 clockwise from (32.325, 6.65) to (32.025, 6.95)
extrude "Extrude51" add sketch "PTT Switch Side Rail Sketch" blind 4.51 from offset 7.49
sketch "PTT Switch Side Rail Sketch (1)" plane through (0, 0, 0) normal (0, 0, 1) x axis (1, 0, 0)
  line L1 (36.675, 16.55) -> (32.325, 16.55)
  line L2 (36.975, 17.05) -> (36.975, 16.85)
  line L3 (32.325, 17.35) -> (36.675, 17.35)
  line L4 (32.025, 16.85) -> (32.025, 17.05)
  arc A1 centre (36.675, 16.85) radius 0.3 clockwise from (36.975, 16.85) to (36.675, 16.55)
  arc A2 centre (36.675, 17.05) radius 0.3 clockwise from (36.675, 17.35) to (36.975, 17.05)
  arc A3 centre (32.325, 17.05) radius 0.3 clockwise from (32.025, 17.05) to (32.325, 17.35)
  arc A4 centre (32.325, 16.85) radius 0.3 clockwise from (32.325, 16.55) to (32.025, 16.85)
extrude "Extrude52" add sketch "PTT Switch Side Rail Sketch (1)" blind 4.51 from offset 7.49
sketch "PTT Switch Actuator Shoulder Sketch" plane through (0, 0, 0) normal (0, 0, 1) x axis (1, 0, 0)
  line L1 (37.28, 6.65) -> (37.22, 6.65)
  line L2 (37.5, 17.13) -> (37.5, 6.87)
  line L3 (37.22, 17.35) -> (37.28, 17.35)
  line L4 (37, 6.87) -> (37, 17.13)
  arc A1 centre (37.28, 6.87) radius 0.22 clockwise from (37.5, 6.87) to (37.28, 6.65)
  arc A2 centre (37.28, 17.13) radius 0.22 clockwise from (37.28, 17.35) to (37.5, 17.13)
  arc A3 centre (37.22, 17.13) radius 0.22 clockwise from (37, 17.13) to (37.22, 17.35)
  arc A4 centre (37.22, 6.87) radius 0.22 clockwise from (37.22, 6.65) to (37, 6.87)
extrude "Extrude53" add sketch "PTT Switch Actuator Shoulder Sketch" blind 4.51 from offset 7.49
sketch "PTT Actuator Passage Sketch" plane through (0, 0, 0) normal (1, 0, 0) x axis (0, 0, -1)
  line L1 (-14.4, 10.6) -> (-16, 10.6)
  line L2 (-13.8, 12.8) -> (-13.8, 11.2)
  line L3 (-16, 13.4) -> (-14.4, 13.4)
  line L4 (-16.6, 11.2) -> (-16.6, 12.8)
  arc A1 centre (-14.4, 11.2) radius 0.6 clockwise from (-13.8, 11.2) to (-14.4, 10.6)
  arc A2 centre (-14.4, 12.8) radius 0.6 clockwise from (-14.4, 13.4) to (-13.8, 12.8)
  arc A3 centre (-16, 12.8) radius 0.6 clockwise from (-16.6, 12.8) to (-16, 13.4)
  arc A4 centre (-16, 11.2) radius 0.6 clockwise from (-16, 10.6) to (-16.6, 11.2)
extrude "Extrude54" cut sketch "PTT Actuator Passage Sketch" blind 4.2 from offset 35.8
sketch "Volume Up Internal Switch Body Clearance Sketch" plane through (0, 0, 0) normal (1, 0, 0) x axis (0, 0, -1)
  line L1 (-8.49, 17.65) -> (-18.01, 17.65)
  line L2 (-8.04, 27.9) -> (-8.04, 18.1)
  line L3 (-18.01, 28.35) -> (-8.49, 28.35)
  line L4 (-18.46, 18.1) -> (-18.46, 27.9)
  arc A1 centre (-8.49, 18.1) radius 0.45 clockwise from (-8.04, 18.1) to (-8.49, 17.65)
  arc A2 centre (-8.49, 27.9) radius 0.45 clockwise from (-8.49, 28.35) to (-8.04, 27.9)
  arc A3 centre (-18.01, 27.9) radius 0.45 clockwise from (-18.46, 27.9) to (-18.01, 28.35)
  arc A4 centre (-18.01, 18.1) radius 0.45 clockwise from (-18.01, 17.65) to (-18.46, 18.1)
extrude "Extrude55" cut sketch "Volume Up Internal Switch Body Clearance Sketch" blind -5.1 (= "-( 5.10 mm )") from offset -31.9
sketch "Volume Up Switch Cage Anchor Sketch" plane through (0, 0, 0) normal (0, 0, 1) x axis (1, 0, 0)
  line L1 (-31.5, 17.45) -> (-32, 17.45)
  line L2 (-31.15, 18.3) -> (-31.15, 17.8)
  line L3 (-32, 18.65) -> (-31.5, 18.65)
  line L4 (-32.35, 17.8) -> (-32.35, 18.3)
  arc A1 centre (-31.5, 17.8) radius 0.35 clockwise from (-31.15, 17.8) to (-31.5, 17.45)
  arc A2 centre (-31.5, 18.3) radius 0.35 clockwise from (-31.5, 18.65) to (-31.15, 18.3)
  arc A3 centre (-32, 18.3) radius 0.35 clockwise from (-32.35, 18.3) to (-32, 18.65)
  arc A4 centre (-32, 17.8) radius 0.35 clockwise from (-32, 17.45) to (-32.35, 17.8)
extrude "Extrude56" add sketch "Volume Up Switch Cage Anchor Sketch" blind 5.59 from offset 2
sketch "Volume Up Switch Cage Anchor Sketch (1)" plane through (0, 0, 0) normal (0, 0, 1) x axis (1, 0, 0)
  line L1 (-31.5, 27.35) -> (-32, 27.35)
  line L2 (-31.15, 28.2) -> (-31.15, 27.7)
  line L3 (-32, 28.55) -> (-31.5, 28.55)
  line L4 (-32.35, 27.7) -> (-32.35, 28.2)
  arc A1 centre (-31.5, 27.7) radius 0.35 clockwise from (-31.15, 27.7) to (-31.5, 27.35)
  arc A2 centre (-31.5, 28.2) radius 0.35 clockwise from (-31.5, 28.55) to (-31.15, 28.2)
  arc A3 centre (-32, 28.2) radius 0.35 clockwise from (-32.35, 28.2) to (-32, 28.55)
  arc A4 centre (-32, 27.7) radius 0.35 clockwise from (-32, 27.35) to (-32.35, 27.7)
extrude "Extrude57" add sketch "Volume Up Switch Cage Anchor Sketch (1)" blind 5.59 from offset 2
sketch "Volume Up Switch Floor Sketch" plane through (0, 0, 0) normal (0, 0, 1) x axis (1, 0, 0)
  line L1 (-31.55, 17.65) -> (-36.65, 17.65)
  line L2 (-31.1, 27.9) -> (-31.1, 18.1)
  line L3 (-36.65, 28.35) -> (-31.55, 28.35)
  line L4 (-37.1, 18.1) -> (-37.1, 27.9)
  arc A1 centre (-31.55, 18.1) radius 0.45 clockwise from (-31.1, 18.1) to (-31.55, 17.65)
  arc A2 centre (-31.55, 27.9) radius 0.45 clockwise from (-31.55, 28.35) to (-31.1, 27.9)
  arc A3 centre (-36.65, 27.9) radius 0.45 clockwise from (-37.1, 27.9) to (-36.65, 28.35)
  arc A4 centre (-36.65, 18.1) radius 0.45 clockwise from (-36.65, 17.65) to (-37.1, 18.1)
extrude "Extrude58" add sketch "Volume Up Switch Floor Sketch" blind 0.55 from offset 7.49
sketch "Volume Up Switch Inward Backstop Sketch" plane through (0, 0, 0) normal (0, 0, 1) x axis (1, 0, 0)
  line L1 (-31.65, 17.65) -> (-31.85, 17.65)
  line L2 (-31.3, 28) -> (-31.3, 18)
  line L3 (-31.85, 28.35) -> (-31.65, 28.35)
  line L4 (-32.2, 18) -> (-32.2, 28)
  arc A1 centre (-31.65, 18) radius 0.35 clockwise from (-31.3, 18) to (-31.65, 17.65)
  arc A2 centre (-31.65, 28) radius 0.35 clockwise from (-31.65, 28.35) to (-31.3, 28)
  arc A3 centre (-31.85, 28) radius 0.35 clockwise from (-32.2, 28) to (-31.85, 28.35)
  arc A4 centre (-31.85, 18) radius 0.35 clockwise from (-31.85, 17.65) to (-32.2, 18)
extrude "Extrude59" add sketch "Volume Up Switch Inward Backstop Sketch" blind 4.51 from offset 7.49
sketch "Volume Up Switch Side Rail Sketch" plane through (0, 0, 0) normal (0, 0, 1) x axis (1, 0, 0)
  line L1 (-32.325, 17.65) -> (-36.675, 17.65)
  line L2 (-32.025, 18.15) -> (-32.025, 17.95)
  line L3 (-36.675, 18.45) -> (-32.325, 18.45)
  line L4 (-36.975, 17.95) -> (-36.975, 18.15)
  arc A1 centre (-32.325, 17.95) radius 0.3 clockwise from (-32.025, 17.95) to (-32.325, 17.65)
  arc A2 centre (-32.325, 18.15) radius 0.3 clockwise from (-32.325, 18.45) to (-32.025, 18.15)
  arc A3 centre (-36.675, 18.15) radius 0.3 clockwise from (-36.975, 18.15) to (-36.675, 18.45)
  arc A4 centre (-36.675, 17.95) radius 0.3 clockwise from (-36.675, 17.65) to (-36.975, 17.95)
extrude "Extrude60" add sketch "Volume Up Switch Side Rail Sketch" blind 4.51 from offset 7.49
sketch "Volume Up Switch Side Rail Sketch (1)" plane through (0, 0, 0) normal (0, 0, 1) x axis (1, 0, 0)
  line L1 (-32.325, 27.55) -> (-36.675, 27.55)
  line L2 (-32.025, 28.05) -> (-32.025, 27.85)
  line L3 (-36.675, 28.35) -> (-32.325, 28.35)
  line L4 (-36.975, 27.85) -> (-36.975, 28.05)
  arc A1 centre (-32.325, 27.85) radius 0.3 clockwise from (-32.025, 27.85) to (-32.325, 27.55)
  arc A2 centre (-32.325, 28.05) radius 0.3 clockwise from (-32.325, 28.35) to (-32.025, 28.05)
  arc A3 centre (-36.675, 28.05) radius 0.3 clockwise from (-36.975, 28.05) to (-36.675, 28.35)
  arc A4 centre (-36.675, 27.85) radius 0.3 clockwise from (-36.675, 27.55) to (-36.975, 27.85)
extrude "Extrude61" add sketch "Volume Up Switch Side Rail Sketch (1)" blind 4.51 from offset 7.49
sketch "Volume Up Switch Actuator Shoulder Sketch" plane through (0, 0, 0) normal (0, 0, 1) x axis (1, 0, 0)
  line L1 (-37.22, 17.65) -> (-37.28, 17.65)
  line L2 (-37, 28.13) -> (-37, 17.87)
  line L3 (-37.28, 28.35) -> (-37.22, 28.35)
  line L4 (-37.5, 17.87) -> (-37.5, 28.13)
  arc A1 centre (-37.22, 17.87) radius 0.22 clockwise from (-37, 17.87) to (-37.22, 17.65)
  arc A2 centre (-37.22, 28.13) radius 0.22 clockwise from (-37.22, 28.35) to (-37, 28.13)
  arc A3 centre (-37.28, 28.13) radius 0.22 clockwise from (-37.5, 28.13) to (-37.28, 28.35)
  arc A4 centre (-37.28, 17.87) radius 0.22 clockwise from (-37.28, 17.65) to (-37.5, 17.87)
extrude "Extrude62" add sketch "Volume Up Switch Actuator Shoulder Sketch" blind 4.51 from offset 7.49
sketch "Volume Up Actuator Passage Sketch" plane through (0, 0, 0) normal (1, 0, 0) x axis (0, 0, -1)
  line L1 (-14.4, 21.6) -> (-16, 21.6)
  line L2 (-13.8, 23.8) -> (-13.8, 22.2)
  line L3 (-16, 24.4) -> (-14.4, 24.4)
  line L4 (-16.6, 22.2) -> (-16.6, 23.8)
  arc A1 centre (-14.4, 22.2) radius 0.6 clockwise from (-13.8, 22.2) to (-14.4, 21.6)
  arc A2 centre (-14.4, 23.8) radius 0.6 clockwise from (-14.4, 24.4) to (-13.8, 23.8)
  arc A3 centre (-16, 23.8) radius 0.6 clockwise from (-16.6, 23.8) to (-16, 24.4)
  arc A4 centre (-16, 22.2) radius 0.6 clockwise from (-16, 21.6) to (-16.6, 22.2)
extrude "Extrude63" cut sketch "Volume Up Actuator Passage Sketch" blind -4.2 (= "-( 4.20 mm )") from offset -35.8
sketch "Volume Down Internal Switch Body Clearance Sketch" plane through (0, 0, 0) normal (1, 0, 0) x axis (0, 0, -1)
  line L1 (-8.49, -11.35) -> (-18.01, -11.35)
  line L2 (-8.04, -1.1) -> (-8.04, -10.9)
  line L3 (-18.01, -0.65) -> (-8.49, -0.65)
  line L4 (-18.46, -10.9) -> (-18.46, -1.1)
  arc A1 centre (-8.49, -10.9) radius 0.45 clockwise from (-8.04, -10.9) to (-8.49, -11.35)
  arc A2 centre (-8.49, -1.1) radius 0.45 clockwise from (-8.49, -0.65) to (-8.04, -1.1)
  arc A3 centre (-18.01, -1.1) radius 0.45 clockwise from (-18.46, -1.1) to (-18.01, -0.65)
  arc A4 centre (-18.01, -10.9) radius 0.45 clockwise from (-18.01, -11.35) to (-18.46, -10.9)
extrude "Extrude64" cut sketch "Volume Down Internal Switch Body Clearance Sketch" blind -5.1 (= "-( 5.10 mm )") from offset -31.9
sketch "Volume Down Switch Cage Anchor Sketch" plane through (0, 0, 0) normal (0, 0, 1) x axis (1, 0, 0)
  line L1 (-31.5, -11.55) -> (-32, -11.55)
  line L2 (-31.15, -10.7) -> (-31.15, -11.2)
  line L3 (-32, -10.35) -> (-31.5, -10.35)
  line L4 (-32.35, -11.2) -> (-32.35, -10.7)
  arc A1 centre (-31.5, -11.2) radius 0.35 clockwise from (-31.15, -11.2) to (-31.5, -11.55)
  arc A2 centre (-31.5, -10.7) radius 0.35 clockwise from (-31.5, -10.35) to (-31.15, -10.7)
  arc A3 centre (-32, -10.7) radius 0.35 clockwise from (-32.35, -10.7) to (-32, -10.35)
  arc A4 centre (-32, -11.2) radius 0.35 clockwise from (-32, -11.55) to (-32.35, -11.2)
extrude "Extrude65" add sketch "Volume Down Switch Cage Anchor Sketch" blind 5.59 from offset 2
